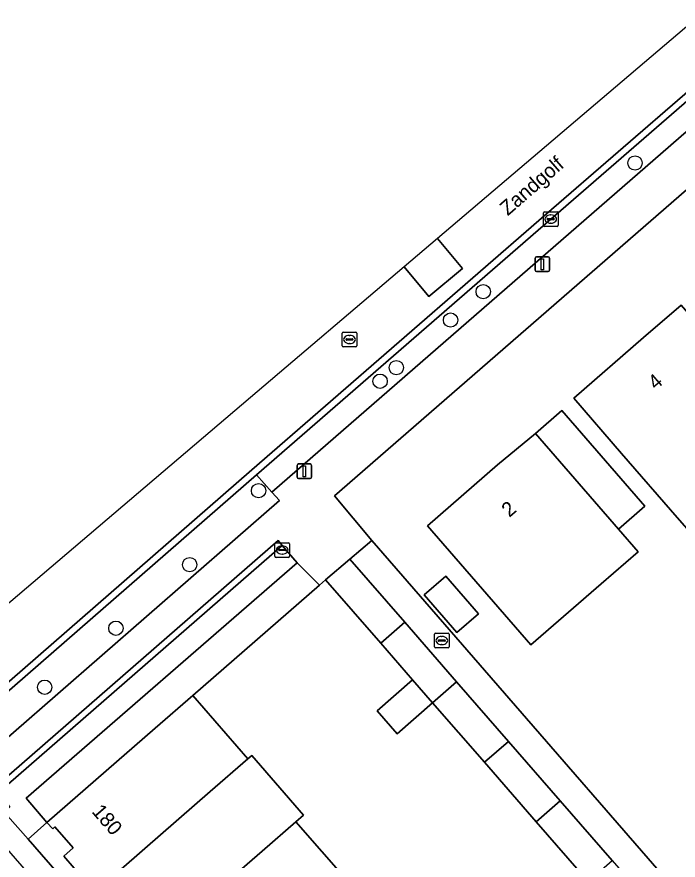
# Model space of a CAD drawing. Extents: x 155887 to 156869, y 383880 to 384678.
# Drawn here: x 156274.5 to 156319.8, y 384353.7 to 384411.3 of the extents above; entities that cross this region are included whole.
import ezdxf

# ---------------------------------------------------------------- set-up
doc = ezdxf.new("R2010")
doc.units = 0
for name, color, linetype in [('IMGEO_Berm_groen', 7, 'Continuous'), ('IMGEO_Boom', 7, 'Continuous'), ('IMGEO_Erf', 7, 'Continuous'), ('IMGEO_Groenvoorziening', 7, 'Continuous'), ('IMGEO_Kolk', 7, 'Continuous'), ('IMGEO_Lichtmast', 7, 'Continuous'), ('IMGEO_Muur', 7, 'Continuous'), ('IMGEO_Openbare_ruimte_label', 7, 'Continuous'), ('IMGEO_Pand', 7, 'Continuous'), ('IMGEO_Pand_nummerreeks', 7, 'Continuous'), ('IMGEO_Parkeervlak_open', 7, 'Continuous'), ('IMGEO_Rijbaan_lokaal_gesloten', 7, 'Continuous'), ('IMGEO_Rijbaan_lokaal_open', 7, 'Continuous'), ('IMGEO_Rioolput', 7, 'Continuous'), ('IMGEO_Voetpad_open', 7, 'Continuous')]:
    doc.layers.add(name, color=color, linetype=linetype)

msp = doc.modelspace()

# ---------------------------------------------------------------- linework, layer by layer
at = {"layer": 'IMGEO_Berm_groen'}
msp.add_lwpolyline([(156292.5, 384378.244), (156291.983, 384378.815), (156290.916, 384379.992), (156269.932, 384361.718), (156269.697, 384361.495), (156271.241, 384359.744)], close=True, dxfattribs=at)
at = {"layer": 'IMGEO_Boom'}
for centre in [(156316.809, 384401.321), (156306.429, 384392.523), (156304.196, 384390.58), (156300.484, 384387.329), (156299.377, 384386.398), (156291.065, 384378.916), (156286.354, 384373.854), (156281.309, 384369.511), (156276.441, 384365.476)]:
    msp.add_circle(centre, 0.489, dxfattribs=at)
at = {"layer": 'IMGEO_Erf'}
for points in [[(156408.123, 384391.086), (156404.4, 384395.417), (156377.02, 384426.898), (156374.487, 384424.698), (156369.682, 384420.523), (156362.599, 384428.676), (156367.375, 384432.826), (156369.937, 384435.051), (156366.216, 384439.396), (156296.268, 384378.553), (156298.818, 384375.511), (156338.119, 384330.3), (156359.041, 384348.401)], [(156327.036, 384383.455), (156331.17, 384378.672), (156326.338, 384374.473), (156323.518, 384377.718), (156321.026, 384375.553), (156319.698, 384377.08), (156315.894, 384381.458), (156312.615, 384385.233), (156317.397, 384389.387), (156319.953, 384391.608), (156323.231, 384387.835)], [(156317.486, 384377.855), (156315.684, 384376.289), (156317.028, 384374.742), (156314.495, 384372.542), (156309.69, 384368.367), (156302.607, 384376.52), (156307.4, 384380.684), (156310.009, 384382.821), (156311.812, 384384.387)], [(156306.102, 384370.504), (156304.628, 384369.223), (156302.399, 384371.788), (156303.874, 384373.069)]]:
    msp.add_lwpolyline(points, close=True, dxfattribs=at)
for points in [[(156313.594, 384352.204), (156310.049, 384356.276), (156306.507, 384360.345), (156302.965, 384364.414), (156300.532, 384362.296), (156299.166, 384363.865), (156301.599, 384365.983), (156299.42, 384368.487), (156295.653, 384372.814), (156295.231, 384372.447), (156286.571, 384364.92), (156290.34, 384360.586), (156290.601, 384360.813), (156294.146, 384356.74), (156293.622, 384356.284), (156297.164, 384352.214)], [(156279.868, 384351.473), (156277.739, 384353.921), (156278.388, 384354.493), (156277.143, 384355.944), (156276.986, 384355.804), (156276.594, 384356.241), (156275.302, 384355.099), (156318.286, 384305.705)]]:
    msp.add_lwpolyline(points, dxfattribs=at)
at = {"layer": 'IMGEO_Groenvoorziening'}
msp.add_lwpolyline([(156295.231, 384372.447), (156293.707, 384373.989), (156275.181, 384357.889), (156276.594, 384356.241), (156283.993, 384362.677), (156286.571, 384364.92)], close=True, dxfattribs=at)
at = {"layer": 'IMGEO_Kolk'}
for p, q in [((156310.622, 384397.984), (156311.474, 384397.984)), ((156310.547, 384397.058), (156310.547, 384397.91)), ((156310.806, 384397.478), (156310.806, 384397.49)), ((156311.244, 384397.441), (156310.846, 384397.441)), ((156310.849, 384397.527), (156311.247, 384397.527)), ((156311.035, 384397.764), (156311.06, 384397.764)), ((156311.29, 384397.49), (156311.29, 384397.478)), ((156311.548, 384397.91), (156311.548, 384397.058)), ((156311.474, 384396.984), (156310.622, 384396.984)), ((156311.058, 384397.204), (156311.033, 384397.204)), ((156292.183, 384374.432), (156292.183, 384375.284)), ((156292.258, 384375.358), (156293.11, 384375.358)), ((156292.485, 384374.901), (156292.883, 384374.901)), ((156292.671, 384375.138), (156292.696, 384375.138)), ((156293.184, 384375.284), (156293.184, 384374.432)), ((156293.11, 384374.358), (156292.258, 384374.358)), ((156292.442, 384374.852), (156292.442, 384374.864)), ((156292.88, 384374.815), (156292.482, 384374.815)), ((156292.694, 384374.578), (156292.669, 384374.578)), ((156292.926, 384374.864), (156292.926, 384374.852)), ((156303.171, 384369.169), (156304.023, 384369.169)), ((156303.096, 384368.243), (156303.096, 384369.095)), ((156303.355, 384368.663), (156303.355, 384368.675)), ((156303.793, 384368.626), (156303.395, 384368.626)), ((156303.398, 384368.712), (156303.796, 384368.712)), ((156303.584, 384368.949), (156303.609, 384368.949)), ((156303.839, 384368.675), (156303.839, 384368.663)), ((156304.097, 384369.095), (156304.097, 384368.243)), ((156304.023, 384368.169), (156303.171, 384368.169)), ((156303.607, 384368.389), (156303.582, 384368.389))]:
    msp.add_line(p, q, dxfattribs=at)
for points in [[(156310.622, 384397.984), (156311.474, 384397.984)], [(156310.547, 384397.058), (156310.547, 384397.91)], [(156311.548, 384397.91), (156311.548, 384397.058)], [(156311.474, 384396.984), (156310.622, 384396.984)], [(156292.183, 384374.432), (156292.183, 384375.284)], [(156292.258, 384375.358), (156293.11, 384375.358)], [(156293.184, 384375.284), (156293.184, 384374.432)], [(156293.11, 384374.358), (156292.258, 384374.358)], [(156303.171, 384369.169), (156304.023, 384369.169)], [(156303.096, 384368.243), (156303.096, 384369.095)], [(156304.097, 384369.095), (156304.097, 384368.243)], [(156304.023, 384368.169), (156303.171, 384368.169)]]:
    msp.add_lwpolyline(points, dxfattribs=at)
for centre, radius, start, end in [((156310.624, 384397.908), 0.0765, 91.55205, 178.44795), ((156310.624, 384397.908), 0.0765, 91.55205, 178.44795), ((156311.472, 384397.908), 0.0765, 1.55205, 88.44795), ((156311.472, 384397.908), 0.0765, 1.55205, 88.44795), ((156310.846, 384397.487), 0.0403, 85.87752, 175.75265), ((156310.843, 384397.477), 0.0366, 178.93798, 274.71019), ((156311.247, 384397.484), 0.043, 264.86636, 352.45326), ((156311.251, 384397.489), 0.0386, 1.73085, 96.63898), ((156310.624, 384397.06), 0.0765, 181.55205, 268.44795), ((156310.624, 384397.06), 0.0765, 181.55205, 268.44795), ((156311.472, 384397.06), 0.0765, 271.55205, 358.44795), ((156311.472, 384397.06), 0.0765, 271.55205, 358.44795), ((156292.26, 384375.282), 0.0765, 91.55205, 178.44795), ((156292.26, 384375.282), 0.0765, 91.55205, 178.44795), ((156292.482, 384374.861), 0.0403, 85.87752, 175.75265), ((156292.887, 384374.863), 0.0386, 1.73085, 96.63898), ((156293.108, 384375.282), 0.0765, 1.55205, 88.44795), ((156293.108, 384375.282), 0.0765, 1.55205, 88.44795), ((156292.26, 384374.434), 0.0765, 181.55205, 268.44795), ((156292.26, 384374.434), 0.0765, 181.55205, 268.44795), ((156292.479, 384374.851), 0.0366, 178.93798, 274.71019), ((156292.883, 384374.858), 0.043, 264.86636, 352.45326), ((156293.108, 384374.434), 0.0765, 271.55205, 358.44795), ((156293.108, 384374.434), 0.0765, 271.55205, 358.44795), ((156303.173, 384369.093), 0.0765, 91.55205, 178.44795), ((156303.173, 384369.093), 0.0765, 91.55205, 178.44795), ((156304.021, 384369.093), 0.0765, 1.55205, 88.44795), ((156304.021, 384369.093), 0.0765, 1.55205, 88.44795), ((156303.395, 384368.672), 0.0403, 85.87752, 175.75265), ((156303.392, 384368.662), 0.0366, 178.93798, 274.71019), ((156303.796, 384368.669), 0.043, 264.86636, 352.45326), ((156303.8, 384368.674), 0.0386, 1.73085, 96.63898), ((156303.173, 384368.245), 0.0765, 181.55205, 268.44795), ((156303.173, 384368.245), 0.0765, 181.55205, 268.44795), ((156304.021, 384368.245), 0.0765, 271.55205, 358.44795), ((156304.021, 384368.245), 0.0765, 271.55205, 358.44795)]:
    msp.add_arc(centre, radius, start, end, dxfattribs=at)
for centre, major_axis, ratio, start_param, end_param in [((156311.034, 384397.484), (-0.387, 0.002), 0.722429, 4.712389, 7.853982), ((156311.059, 384397.484), (-0.39, 0.002), 0.717154, 1.570796, 4.712389), ((156292.67, 384374.858), (-0.387, 0.002), 0.722429, 4.712389, 7.853982), ((156292.695, 384374.858), (-0.39, 0.002), 0.717154, 1.570796, 4.712389), ((156303.583, 384368.669), (-0.387, 0.002), 0.722429, 4.712389, 7.853982), ((156303.608, 384368.669), (-0.39, 0.002), 0.717154, 1.570796, 4.712389)]:
    msp.add_ellipse(centre, major_axis=major_axis, ratio=ratio, start_param=start_param, end_param=end_param, dxfattribs=at)
at = {"layer": 'IMGEO_Lichtmast'}
for p, q in [((156309.97, 384394), (156309.97, 384394.8)), ((156309.97, 384394.8), (156309.97, 384394)), ((156310.07, 384394.9), (156310.86, 384394.9)), ((156310.86, 384394.9), (156310.07, 384394.9)), ((156310.96, 384394.8), (156310.96, 384394)), ((156310.96, 384394), (156310.96, 384394.8)), ((156310.86, 384393.9), (156310.07, 384393.9)), ((156310.07, 384393.9), (156310.86, 384393.9)), ((156293.801, 384380.741), (156294.591, 384380.741)), ((156294.591, 384380.741), (156293.801, 384380.741)), ((156293.701, 384379.841), (156293.701, 384380.641)), ((156293.701, 384380.641), (156293.701, 384379.841)), ((156294.691, 384380.641), (156294.691, 384379.841)), ((156294.691, 384379.841), (156294.691, 384380.641)), ((156294.591, 384379.741), (156293.801, 384379.741)), ((156293.801, 384379.741), (156294.591, 384379.741))]:
    msp.add_line(p, q, dxfattribs=at)
for points in [[(156310.39, 384394.775), (156310.54, 384394.775), (156310.54, 384394.025), (156310.39, 384394.025), (156310.39, 384394.775)], [(156294.121, 384380.616), (156294.271, 384380.616), (156294.271, 384379.866), (156294.121, 384379.866), (156294.121, 384380.616)]]:
    msp.add_lwpolyline(points, dxfattribs=at)
for centre, start, end in [((156310.07, 384394.8), 90, 180), ((156310.07, 384394.8), 90, 180), ((156310.86, 384394.8), 0, 90), ((156310.86, 384394.8), 360, 90), ((156310.07, 384394), 180, 270), ((156310.07, 384394), 180, 270), ((156310.86, 384394), 270, 0), ((156310.86, 384394), 270, 0), ((156293.801, 384380.641), 90, 180), ((156293.801, 384380.641), 90, 180), ((156294.591, 384380.641), 0, 90), ((156294.591, 384380.641), 360, 90), ((156293.801, 384379.841), 180, 270), ((156293.801, 384379.841), 180, 270), ((156294.591, 384379.841), 270, 0), ((156294.591, 384379.841), 270, 0)]:
    msp.add_arc(centre, 0.1, start, end, dxfattribs=at)
at = {"layer": 'IMGEO_Muur'}
msp.add_lwpolyline([(156272.551, 384358.226), (156273.681, 384356.97), (156274.048, 384357.308), (156273.21, 384358.24), (156292.682, 384375.176), (156292.415, 384375.503)], close=True, dxfattribs=at)
for points in [[(156295.231, 384372.447), (156295.653, 384372.814)], [(156283.993, 384362.677), (156295.231, 384372.447)]]:
    msp.add_lwpolyline(points, dxfattribs=at)
at = {"layer": 'IMGEO_Pand'}
for points in [[(156315.894, 384381.458), (156319.698, 384377.08), (156321.026, 384375.553), (156323.518, 384377.718), (156326.338, 384374.473), (156331.17, 384378.672), (156327.036, 384383.455), (156323.231, 384387.835), (156319.953, 384391.608), (156317.397, 384389.387), (156312.615, 384385.233)], [(156310.009, 384382.821), (156315.684, 384376.289), (156317.486, 384377.855), (156311.812, 384384.387)], [(156310.009, 384382.821), (156307.4, 384380.684), (156302.607, 384376.52), (156309.69, 384368.367), (156314.495, 384372.542), (156317.028, 384374.742), (156315.684, 384376.289)], [(156299.42, 384368.487), (156301.064, 384369.918), (156297.298, 384374.244), (156295.653, 384372.814)], [(156306.102, 384370.504), (156303.874, 384373.069), (156302.399, 384371.788), (156304.628, 384369.223)], [(156301.064, 384369.918), (156299.42, 384368.487), (156301.599, 384365.983), (156302.965, 384364.414), (156304.609, 384365.845)], [(156302.965, 384364.414), (156301.599, 384365.983), (156299.166, 384363.865), (156300.532, 384362.296)], [(156302.965, 384364.414), (156306.507, 384360.345), (156308.151, 384361.776), (156304.609, 384365.845)], [(156287.761, 384358.342), (156290.34, 384360.586), (156286.571, 384364.92), (156283.993, 384362.677), (156276.594, 384356.241), (156276.986, 384355.804), (156277.143, 384355.944), (156278.388, 384354.493), (156277.739, 384353.921), (156279.868, 384351.473), (156283.278, 384354.441)], [(156311.693, 384357.707), (156308.151, 384361.776), (156306.507, 384360.345), (156310.049, 384356.276)], [(156293.622, 384356.284), (156294.146, 384356.74), (156290.601, 384360.813), (156290.34, 384360.586), (156287.761, 384358.342), (156283.278, 384354.441), (156279.868, 384351.473), (156280.022, 384351.296), (156280.679, 384351.867), (156281.93, 384350.423), (156281.265, 384349.858), (156283.413, 384347.4), (156291.303, 384354.266)], [(156311.693, 384357.707), (156310.049, 384356.276), (156313.594, 384352.204), (156315.238, 384353.635)], [(156286.945, 384343.322), (156290.588, 384346.492), (156294.842, 384350.194), (156297.164, 384352.214), (156293.622, 384356.284), (156291.303, 384354.266), (156283.413, 384347.4), (156283.561, 384347.23), (156284.216, 384347.802), (156285.462, 384346.358), (156284.805, 384345.788)]]:
    msp.add_lwpolyline(points, close=True, dxfattribs=at)
at = {"layer": 'IMGEO_Parkeervlak_open'}
msp.add_lwpolyline([(156291.983, 384378.815), (156364.212, 384441.65), (156363.215, 384442.778), (156320.848, 384405.981), (156311.048, 384397.484), (156290.916, 384379.992)], close=True, dxfattribs=at)
at = {"layer": 'IMGEO_Rijbaan_lokaal_gesloten'}
for points in [[(156340.891, 384428.127), (156303.292, 384396.148), (156303.292, 384396.148), (156305.005, 384394.094), (156302.71, 384392.18), (156301.015, 384394.212), (156290.516, 384385.282), (156259.242, 384358.683), (156254.318, 384354.295), (156256.971, 384351.247)], [(156263.845, 384351.9), (156268.182, 384354.901), (156267.947, 384355.223), (156267.744, 384355.566), (156267.574, 384355.926), (156267.438, 384356.301), (156267.338, 384356.687), (156267.275, 384357.08), (156267.246, 384357.352), (156267.231, 384357.789), (156267.255, 384358.225), (156267.318, 384358.657), (156267.419, 384359.082), (156267.558, 384359.496), (156267.734, 384359.896), (156267.944, 384360.279), (156268.136, 384360.564), (156268.459, 384360.973), (156268.817, 384361.352), (156269.208, 384361.697), (156290.614, 384380.339), (156310.746, 384397.831), (156320.547, 384406.328)]]:
    msp.add_lwpolyline(points, dxfattribs=at)
at = {"layer": 'IMGEO_Rijbaan_lokaal_open'}
for points in [[(156364.415, 384444.431), (156320.547, 384406.328), (156310.746, 384397.831), (156290.614, 384380.339), (156269.208, 384361.697), (156268.817, 384361.352), (156268.459, 384360.973), (156268.136, 384360.564), (156267.944, 384360.279), (156267.734, 384359.896), (156267.558, 384359.496), (156267.419, 384359.082), (156267.318, 384358.657), (156267.255, 384358.225), (156267.231, 384357.789), (156267.246, 384357.352), (156267.275, 384357.08), (156267.338, 384356.687), (156267.438, 384356.301), (156267.574, 384355.926), (156267.744, 384355.566), (156267.947, 384355.223), (156268.182, 384354.901), (156268.549, 384355.178)], [(156269.697, 384361.495), (156269.932, 384361.718), (156290.916, 384379.992), (156311.048, 384397.484), (156320.848, 384405.981), (156363.215, 384442.778)]]:
    msp.add_lwpolyline(points, dxfattribs=at)
msp.add_lwpolyline([(156301.015, 384394.212), (156302.71, 384392.18), (156305.005, 384394.094), (156303.292, 384396.148), (156303.292, 384396.148)], close=True, dxfattribs=at)
at = {"layer": 'IMGEO_Rioolput'}
for p, q in [((156296.783, 384388.828), (156296.783, 384389.68)), ((156296.858, 384389.754), (156297.71, 384389.754)), ((156297.085, 384389.297), (156297.483, 384389.297)), ((156297.271, 384389.534), (156297.296, 384389.534)), ((156297.784, 384389.68), (156297.784, 384388.828)), ((156297.71, 384388.754), (156296.858, 384388.754)), ((156297.042, 384389.248), (156297.042, 384389.26)), ((156297.48, 384389.211), (156297.082, 384389.211)), ((156297.294, 384388.974), (156297.269, 384388.974)), ((156297.526, 384389.26), (156297.526, 384389.248))]:
    msp.add_line(p, q, dxfattribs=at)
for points in [[(156296.783, 384388.828), (156296.783, 384389.68)], [(156296.858, 384389.754), (156297.71, 384389.754)], [(156297.784, 384389.68), (156297.784, 384388.828)], [(156297.71, 384388.754), (156296.858, 384388.754)]]:
    msp.add_lwpolyline(points, dxfattribs=at)
for centre, radius, start, end in [((156296.86, 384389.678), 0.0765, 91.55205, 178.44795), ((156296.86, 384389.678), 0.0765, 91.55205, 178.44795), ((156297.082, 384389.257), 0.0403, 85.87752, 175.75265), ((156297.487, 384389.259), 0.0386, 1.73085, 96.63898), ((156297.708, 384389.678), 0.0765, 1.55205, 88.44795), ((156297.708, 384389.678), 0.0765, 1.55205, 88.44795), ((156296.86, 384388.83), 0.0765, 181.55205, 268.44795), ((156296.86, 384388.83), 0.0765, 181.55205, 268.44795), ((156297.079, 384389.247), 0.0366, 178.93798, 274.71019), ((156297.483, 384389.254), 0.043, 264.86636, 352.45326), ((156297.708, 384388.83), 0.0765, 271.55205, 358.44795), ((156297.708, 384388.83), 0.0765, 271.55205, 358.44795)]:
    msp.add_arc(centre, radius, start, end, dxfattribs=at)
for centre, major_axis, ratio, start_param, end_param in [((156297.27, 384389.254), (-0.387, 0.002), 0.722429, 4.712389, 7.853982), ((156297.295, 384389.254), (-0.39, 0.002), 0.717154, 1.570796, 4.712389)]:
    msp.add_ellipse(centre, major_axis=major_axis, ratio=ratio, start_param=start_param, end_param=end_param, dxfattribs=at)
at = {"layer": 'IMGEO_Voetpad_open'}
for points in [[(156296.268, 384378.553), (156366.216, 384439.396), (156364.212, 384441.65), (156291.983, 384378.815), (156292.5, 384378.244), (156271.241, 384359.744), (156269.697, 384361.495)], [(156268.549, 384355.178), (156268.595, 384355.21), (156271.108, 384356.976), (156271.403, 384357.221), (156272.551, 384358.226), (156292.415, 384375.503), (156292.682, 384375.176), (156293.707, 384373.989), (156295.231, 384372.447), (156295.653, 384372.814), (156297.298, 384374.244), (156298.818, 384375.511), (156296.268, 384378.553)]]:
    msp.add_lwpolyline(points, dxfattribs=at)
for points in [[(156298.818, 384375.511), (156297.298, 384374.244), (156301.064, 384369.918), (156304.609, 384365.845), (156308.151, 384361.776), (156311.693, 384357.707), (156315.238, 384353.635), (156318.837, 384349.501), (156322.416, 384345.389), (156325.958, 384341.321), (156329.516, 384337.232), (156333.055, 384333.167), (156336.59, 384329.107), (156338.119, 384330.3)], [(156293.707, 384373.989), (156292.682, 384375.176), (156273.21, 384358.24), (156274.048, 384357.308), (156273.681, 384356.97), (156273.892, 384356.68), (156275.302, 384355.099), (156276.594, 384356.241), (156275.181, 384357.889)], [(156275.302, 384355.099), (156273.892, 384356.68), (156272.739, 384355.693), (156278.83, 384348.702), (156279.844, 384347.539), (156287.277, 384338.997), (156286.992, 384338.753), (156316.791, 384304.393), (156318.286, 384305.705)]]:
    msp.add_lwpolyline(points, close=True, dxfattribs=at)

# ---------------------------------------------------------------- texts
at = {"layer": 'IMGEO_Openbare_ruimte_label'}
msp.add_text('Zandgolf', height=1, rotation=40.98653, dxfattribs=at).set_placement((156308.104, 384397.669))
at = {"layer": 'IMGEO_Pand_nummerreeks'}
for s, rotation, p in [('4', 40.98298, (156318.228, 384385.764)), ('2', 40.98367, (156308.217, 384377.049)), ('180', 310.972, (156279.612, 384356.949))]:
    msp.add_text(s, height=1, rotation=rotation, dxfattribs=at).set_placement(p)

doc.saveas('drawing.dxf')
